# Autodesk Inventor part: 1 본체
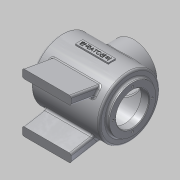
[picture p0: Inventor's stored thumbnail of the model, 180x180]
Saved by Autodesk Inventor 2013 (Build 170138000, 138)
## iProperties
Created: 2015-01
Part Number: 1 본체
Material: 알루미늄 6061
Document SubType Name: Modeling
Designer: Administrator
Density: 2.71 g/cm^3
Mass: 1019.02 g
Surface Area: 1069.83 cm^2
Volume: 376.023 cm^3
Author: Administrator
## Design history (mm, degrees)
sketch "스케치1"
  geometry: C1 r 50 at (0, 0); 1 further point
  constraints: 1 centre point, 1 coincident
  dimensions: "d0" = 100 diameter of C1
extrude "돌출1" new body sketch "스케치1" stored distance "d2" = 112; taper "d3" = 0 deg
sketch "스케치2"
  geometry: C1 r 50 at (0, 0) reference; C2 r 38 at (0, 0)
  constraints: 1 centre point, 1 coincident
  dimensions: "d4" = 76 diameter of C2
extrude "돌출2" join sketch "스케치2" distance "d5" = 5; taper "d6" = 0 deg
sketch "스케치4"
  geometry: L1 (61, 38)-(61, -38) reference; L2 (-61, 38)-(-61, -38) reference; L3 (61, 0)-(-61, 0); L4 (49, -45)-(49, 0); L5 (-48, -45)-(-48, 0); L6 (61, 0)-(61, -27); L7 (61, -27)-(49, -27); L8 (-61, 0)-(-61, -27); L9 (-61, -27)-(-48, -27); L10 (-56, 50)-(-56, -50) reference; L11 (56, -50)-(56, 50) reference; L12 (49, -45)-(-48, -45) reference; 3 further points
  constraints: 16 end point, 6 point on line, 5 perpendicular, 3 midpoint, 1 horizontal, 1 vertical alignment
  dimensions: "d11" = 54 diameter of L9 L3; "d12" = 54 diameter of L7 L3; "d59" = 7 distance between parallel lines of L11 L4; "d60" = 8 distance between parallel lines of L10 L5; "d61" = 97 distance of L4.start L5.start (derived); "d62" = 90 diameter of L12 L3 (derived)
revolve "회전1" sketch "스케치4" stored, may be unused: angle "d14" = 90 deg
node "작업 평면1"
sketch "스케치5"
  geometry: L1 (-27, -6)-(27, -6); L2 (27, -6)-(27, 6); L3 (27, 6)-(-27, 6); L4 (-27, 6)-(-27, -6); L5 (-27, -6)-(27, 6); L6 (27, -6)-(-27, 6); 1 further point
  constraints: 12 end point, 2 midpoint, 2 parallel, 1 horizontal, 1 perpendicular
  dimensions: "d15" = 54 distance of L2.end L3.end; "d17" = 12 distance of L1.end L2.end
extrude "돌출3" join sketch "스케치5" distance "d18" = 2; taper "d20" = 0 deg; dims "d19" = 3, "d21" = 0
sketch "스케치6"
  geometry: L1 (-24.887, 3.602)-(24.887, 3.602); L2 (24.887, 3.602)-(24.887, -3.602); L3 (24.887, -3.602)-(-24.887, -3.602); L4 (-24.887, -3.602)-(-24.887, 3.602); L5 (-24.887, 3.602)-(24.887, -3.602); L6 (-24.887, -3.602)-(24.887, 3.602); 2 further points
  constraints: 4 end point, 1 coincident, 1 midpoint, 2 other
feature "엠보싱1" sketch "스케치6" dims "d11" = 54, "d22" = 0.5, "d23" = 0
sketch "스케치7"
  geometry: L1 (0, 0)-(-80, 0); L2 (-80, 48)-(-80, -48); L3 (-80, -48)-(-30.865, -39.336); L4 (-80, -34)-(-41.901, -27.282); L5 (-80, 48)-(-30.865, 39.336); L6 (-80, 34)-(-41.901, 27.282); A1 r 50 centre (0, 0) between (-30.865, -39.336) and (-41.901, -27.282) reference
  constraints: 12 end point, 4 point on circle, 2 parallel, 2 point on line, 1 horizontal, 1 midpoint, 1 perpendicular
  dimensions: "d25" = 80 distance of L1.end L1.start; "d26" = 96 distance of L2.start L2.end; "d27" = 100 deg angle of L3 L2; "d28" = 14 distance of L2.end L4.start; "d29" = 80 deg angle of L2 L4 (derived); "d30" = 14 distance of L6.start L2.start; "d31" = 100 deg angle of L2 L5; "d32" = 80 deg angle of L2 L6 (derived)
extrude "돌출4" join sketch "스케치7" stored distance "d33" = 80; taper "d34" = 0 deg
node "작업 평면3"
node "작업 평면4"
sketch "스케치11"
  geometry: L1 (61, 38)-(61, -38) reference; L2 (-61, 38)-(-61, -38) reference; C1 r 38 at (-1, 0); 1 further point
  constraints: 1 centre point, 1 horizontal alignment
  dimensions: "d101" = 60 distance from line of L2 C1.centre; "d102" = 62 distance from line of C1.centre L1 (derived); "d103" = 76 diameter of C1
extrude "돌출8" join sketch "스케치11" stored distance "d67" = 80; taper "d68" = 0 deg
sketch "스케치14" dims "d84" = 64
  geometry: C1 r 27 at (0, 0) reference; C2 r 38 at (0, 0) reference; 5 further points
  constraints: 2 vertical alignment, 1 coincident, 7 other
  dimensions: "d87" = 360 deg dimension on point (0, 0) point (0, 32) (derived)
hole "구멍3" sketch "스케치14" at (0, 32), (-32, 0), (0, -32), (32, 0) diameter "d89" = 3.242; stored, may be unused: countersink angle "d93" = 90 deg, drill point angle "d95" = 118 deg; dims "d90" = 8, "d91" = 4, "d92" = 2, "d94" = 10
chamfer "모따기1" distance "d96" = 1; stored, may be unused: second distance "d97" = 2, angle "d98" = 45 deg
fillet "모깎기1" dims "d99" = 3
sketch "스케치15"
  geometry: C1 r 38 at (0, 0) reference; C2 r 27 at (0, 0); 1 further point
  constraints: 1 centre point, 1 coincident
  dimensions: "d104" = 54 diameter of C2
extrude "돌출10" cut sketch "스케치15" stored distance "d105" = 80; taper "d106" = 0 deg
sketch "스케치16" dims "d108" = 64
  geometry: C1 r 27 at (0, 0) reference; C2 r 38 at (0, 0) reference; 6 further points
  constraints: 2 vertical alignment, 1 coincident, 7 other
  dimensions: "d111" = 360 deg dimension on point (0, 0) point (0, 32) (derived)
hole "구멍4" sketch "스케치16" at (0, 32), (-32, 0), (0, -32), (32, 0) diameter "d113" = 3.242; stored, may be unused: countersink angle "d117" = 90 deg, drill point angle "d119" = 118 deg; dims "d114" = 8, "d115" = 4, "d116" = 2, "d118" = 10
fillet "모깎기2" dims "d120" = 3
node "솔리드1"
mirror "대칭2"
mirror "대칭3"
other parameters: "d35" = 62, "d65" = 62
